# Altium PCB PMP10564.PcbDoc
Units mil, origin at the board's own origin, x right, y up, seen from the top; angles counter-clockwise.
Board outline 4200 x 3100 mil, 2 copper layers (Top Layer, Bottom Layer), stack 62 mil thick; 67 components, 34 nets, 153 pads, 5 vias.
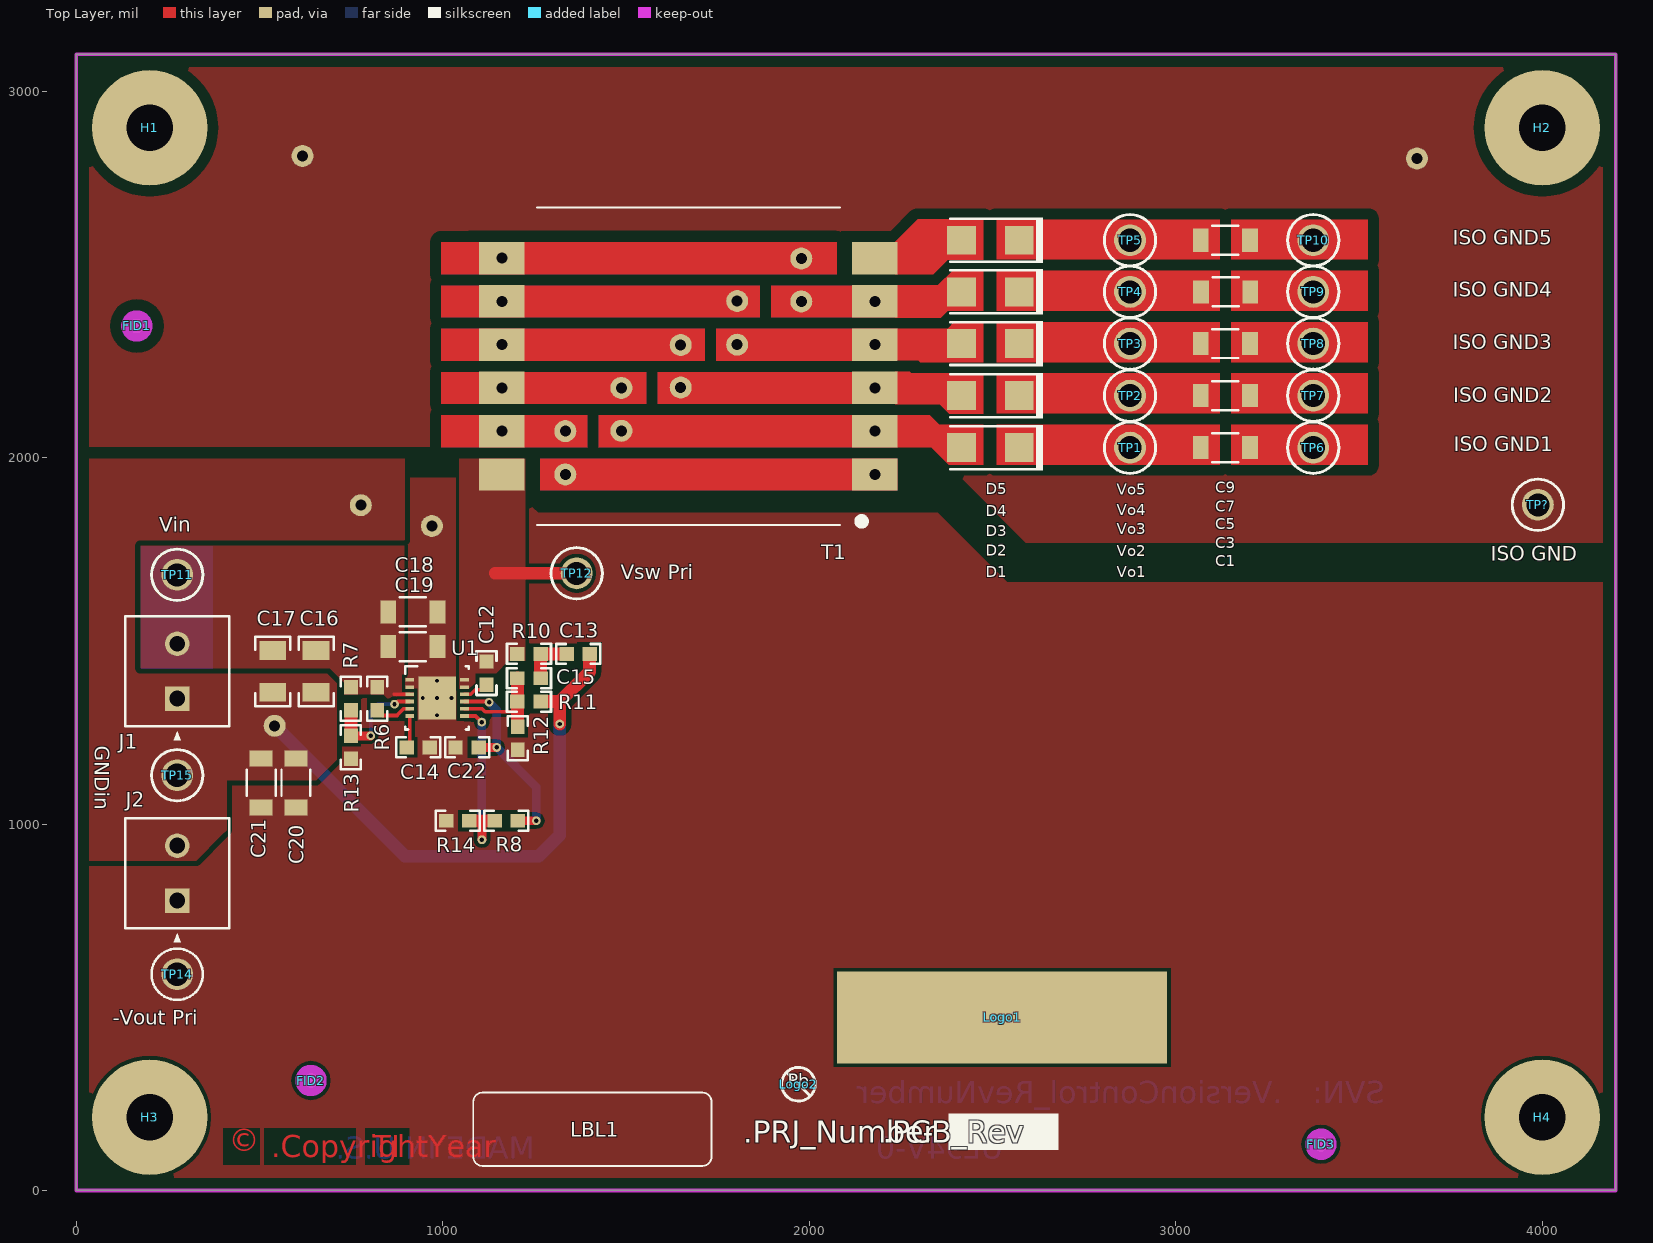
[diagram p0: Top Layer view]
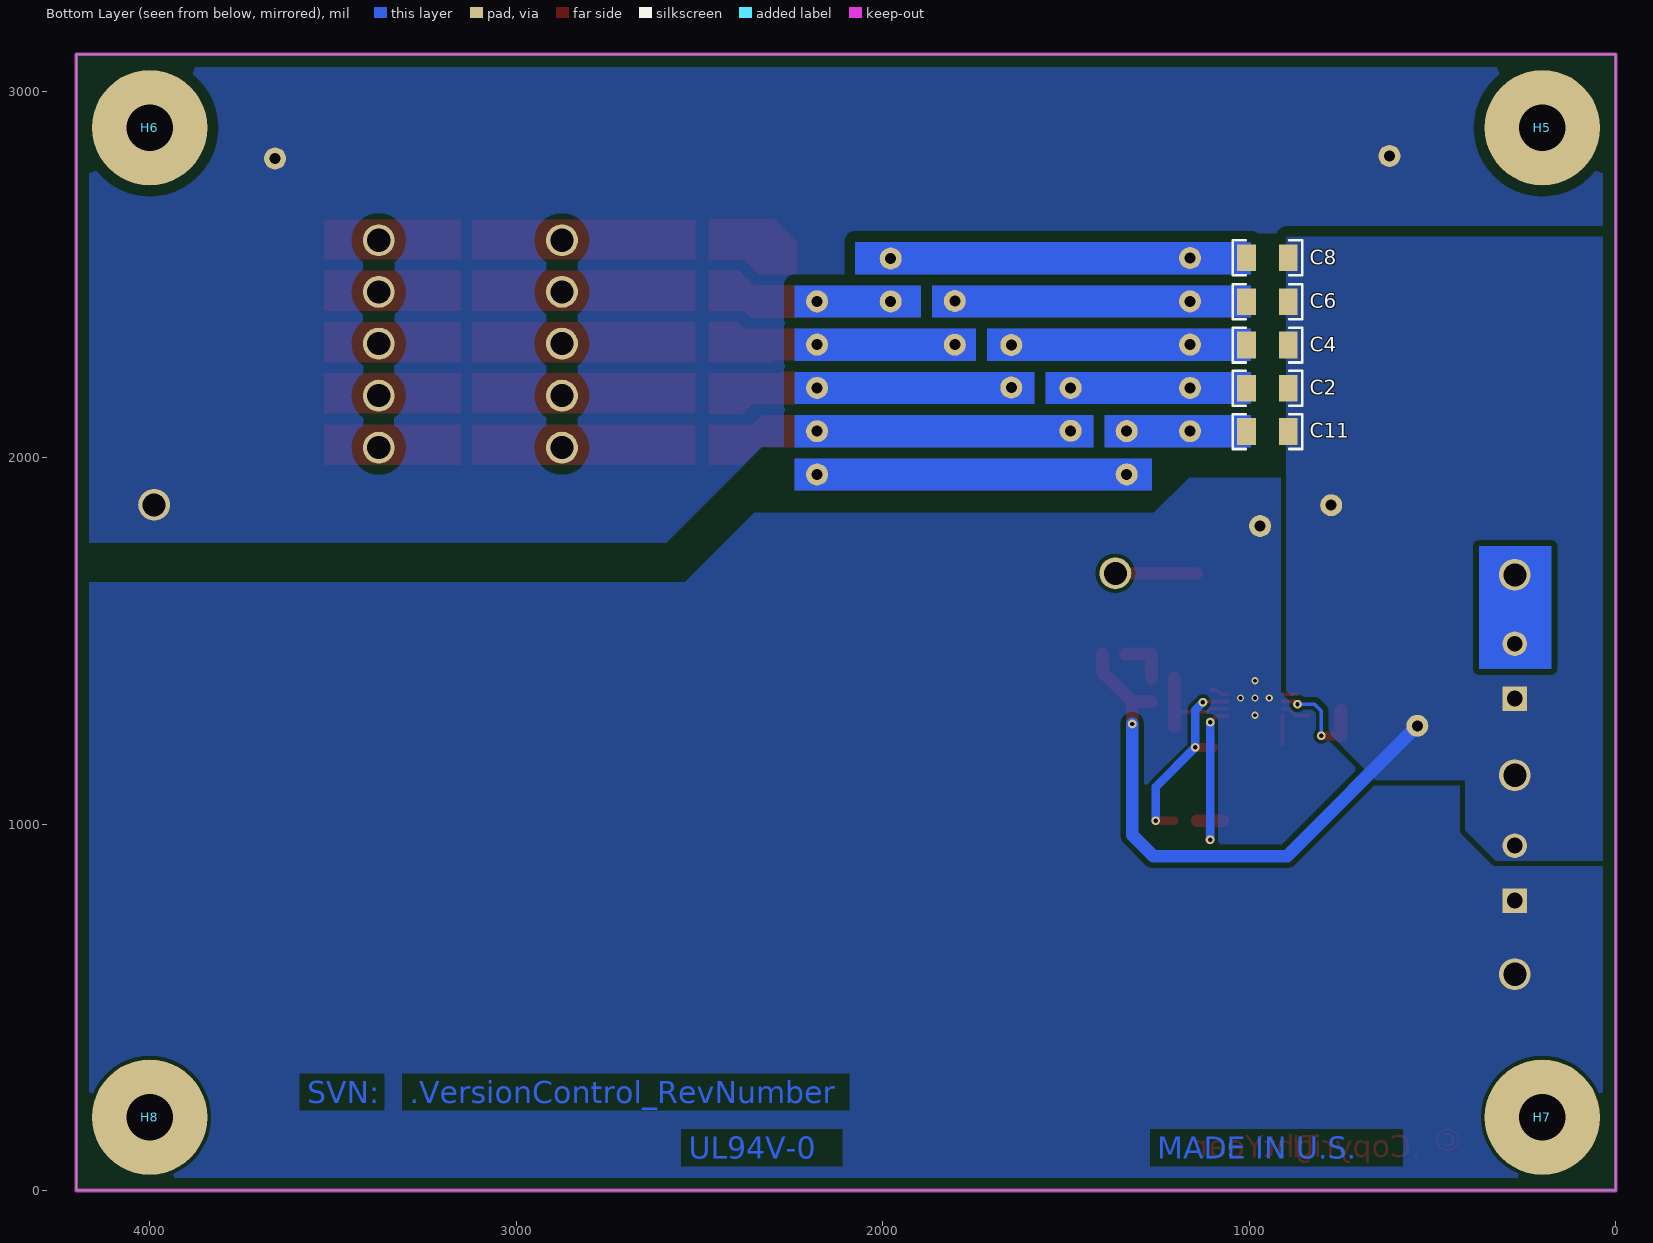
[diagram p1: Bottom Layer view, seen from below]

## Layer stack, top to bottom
Top Layer: signal copper 1.4
Dielectric: core 59.2, FR-4, Dk 4.8
Bottom Layer: signal copper 1.4

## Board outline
0,0 4200,0 4200,3100 0,3100

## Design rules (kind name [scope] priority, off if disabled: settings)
AcuteAngle [All] p1: minimum=4.50000000000000E+0001 checktracksonly=FALSE
AssemblyTestPointUsage [All] p1: valid=2
Clearance "Clearance_ISO GND Bottom" [InNet('ISO GND') vs InNet('GND')] p1: gap=30
Clearance Clearance_KeepOut [OnLayer('Keep-Out Layer')] p2: gap=30
Clearance Clearance_GND [InNet('GND')] p3: gap=15
Clearance Clearance_-Vout [InNet('-VOUT')] p4: gap=10
Clearance "Clearance_ISO GND" [InNet('ISO GND')] p5: gap=30
Clearance Clearance_BoardEdge_MountingHoles [OnCopper and InComponentClass('Mounting Holes') vs IsKeepOut] p6: gap=35
Clearance Clearance_BoardEdge_Poly [OnCopper and InPoly vs IsKeepOut] p7: gap=25
Clearance Clearance_BoardEdge [OnCopper and Not InComponentClass('Logo') and not InComponentClass('FiducialMark') and not InRegion(1000,500,4000,800) and Not IsKeepout vs IsKeepOut] p8: gap=25
Clearance Clearance_Poly [InPolygon] p9: gap=9
Clearance [All] p10: gap=9
ComponentClearance ComponentClearance_Shunt [InComponentClass('Header') vs InComponentClass('Shunt')] p1: gap=0 collisioncheckmode=3 verticalgap=0 showdistances=FALSE
ComponentClearance ComponentClearance_MountingHoles_FiducialMarks [InComponentClass('Mounting Holes') vs InComponentClass('FiducialMark')] p2: gap=30 collisioncheckmode=3 verticalgap=10 showdistances=FALSE
ComponentClearance ComponentClearance_Logo [InComponentClass('Logo')] p3: gap=30 collisioncheckmode=3 verticalgap=10 showdistances=FALSE
ComponentClearance ComponentClearance_ScrewToNut [(HasFootprint('NY PMS 440 0025 PH')) vs (HasFootprint('Keystone_1902C'))] p4: gap=5 collisioncheckmode=3 verticalgap=10 showdistances=FALSE
ComponentClearance ComponentClearance_MountingHoles [InComponentClass('Mounting Holes')] p5: gap=200 collisioncheckmode=3 verticalgap=100000 showdistances=FALSE
ComponentClearance ComponentClearance_SmallPassives [HasFootprint('0201*') or HasFootprint('0402*') or HasFootprint('0508') or HasFootprint('0603*') or HasFootprint('0612') or HasFootprint('0805*') or HasFootprint('0815*') or HasFootprint('0830*') or HasFootprint('1206*') or HasFootprint('1210*') or HasFootprint('1808*') or HasFootprint('1812*') or HasFootprint('1825*') or HasFootprint('2010*') or HasFootprint('2220*') or HasFootprint('2225*') or HasFootprint('2512*') or HasFootprint('2728*') or HasFootprint('3518*') vs HasFootprint('0201*') or HasFootprint('0402*') or HasFootprint('0508') or HasFootprint('0603*') or HasFootprint('0612') or HasFootprint('0805*') or HasFootprint('0815*') or HasFootprint('0830*') or HasFootprint('1206*') or HasFootprint('1210*') or HasFootprint('1808*') or HasFootprint('1812*') or HasFootprint('1825*') or HasFootprint('2010*') or HasFootprint('2220*') or HasFootprint('2225*') or HasFootprint('2512*') or HasFootprint('2728*') or HasFootprint('3518*')] p6: gap=20 collisioncheckmode=3 verticalgap=10 showdistances=FALSE
ComponentClearance ComponentClearance_THtoSMT [IsThruComponent vs IsSMTComponent] p7: gap=30 collisioncheckmode=3 verticalgap=30 showdistances=FALSE
ComponentClearance ComponentClearance_THtoTH [IsThruComponent vs IsThruComponent] p8: gap=15 collisioncheckmode=3 verticalgap=30 showdistances=FALSE
ComponentClearance [All] p9: gap=20 collisioncheckmode=3 verticalgap=10 showdistances=FALSE
DiffPairsRouting [All] p1: maxlimit=100 minlimit=10 mostfreqgap=10 maxuncoupledlength=1000
FabricationTestPointUsage TestPointUsage [All] p1: valid=2 allowmultiple=FALSE
FabricationTestpoint Testpoint [All] p1: side=3 testpointundercomponent=TRUE minsize=40 maxsize=100 preferedsize=60 minholesize=0 maxholesize=40 preferedholesize=32 testpointgrid=1 allowsidetop=TRUE allowsidebottom=TRUE usegrid=TRUE gridtolerance=0.01
FanoutControl Fanout_LCC [IsLCC] p1: bgadir=Out bgaviamode=Centered fanoutstyle=Auto fanoutdirection=Alternating viagrid=1 // Fanout_LCC (Default Rule)
FanoutControl Fanout_BGA [IsBGA] p2: bgadir=Out bgaviamode=Centered fanoutstyle=Auto fanoutdirection=Alternating viagrid=1 // Fanout_BGA (Default Rule)
FanoutControl Fanout_Default [All] p4: bgadir=Out bgaviamode=Centered fanoutstyle=Auto fanoutdirection=Alternating viagrid=1 // Fanout_Default (Default Rule)
FanoutControl Fanout_Small [(CompPinCount < 5)] p5: bgadir=Out bgaviamode=Centered fanoutstyle=Auto fanoutdirection=OutThenIn viagrid=1 // Fanout_Small (Default Rule)
HoleSize [All] p1: absolutevalues=TRUE maxlimit=251 minlimit=8 maxpercent=80.000 minpercent=20.000
MinimumAnnularRing MinimumAnnularRing_ThermalPadVias [IsVia and InAnyComponent] p1: minimumring=5
MinimumAnnularRing [All] p2: minimumring=5
MinimumSolderMaskSliver MinimumSolderMaskSliver_Logo [InComponentClass('Logo') vs InComponentClass('Logo')] p1: minsoldermaskwidth=0.7
MinimumSolderMaskSliver [All] p2: minsoldermaskwidth=3.94
PlaneClearance [All] p1: clearance=15
PlaneConnect [All] p1: planeconnectstyle=Direct reliefexpansion=10 reliefentries=4 reliefconductorwidth=10 reliefairgap=10
PolygonConnect [All] p1: connectstyle=Direct reliefconductorwidth=10 reliefentries=4 polygonreliefangle="90 Angle" airgapwidth=10
RoutingVias ThermalPadVias [IsVia and InAnyComponent] p1: holewidth=7.87 width=19.68 viastyle="Through Hole" minholewidth=7.87 minwidth=19.68 maxholewidth=12.99 maxwidth=23.62
RoutingVias [All] p2: holewidth=16 width=34 viastyle="Through Hole" minholewidth=7.87 minwidth=26 maxholewidth=40 maxwidth=65
SMDToCorner [All] p1: distance=30000
SilkToSilkClearance SilkToSilkClearance_Pb-FreeLogo [(HasFootprint('Pb-Free_Overlay_Medium') OR HasFootprint('Pb-Free_Overlay_Small')) vs (HasFootprint('Pb-Free_Overlay_Medium') OR HasFootprint('Pb-Free_Overlay_Small'))] p1: silktosilkclearance=0
SilkToSilkClearance [All] p2: silktosilkclearance=5
SilkscreenOverComponentPads [All] p1: minsilkscreentomaskgap=5
SolderMaskExpansion [All] p1: expansion=1.97
Width [All] p1: maxlimit=100 minlimit=6 preferedwidth=10 checkconnectedcopper=TRUE
13 further rules are at their usual default settings.

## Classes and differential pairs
component class "PMP10564 Schematics": C1 C2 C3 C4 C5 C6 C7 C8 C9 C11 C12 C13 C14 C15 C16 C17 C18 C19 C20 C21 C22 D1 D2 D3 D4 D5 J1 J2 R6 R7 R8 R10 R11 R12 R13 R14 T1 TP1 TP2 TP3 TP4 TP5 TP6 TP7 TP8 TP9 TP10 TP11 TP12 TP14 TP15 TP? U1
component class "Mounting Holes": H1 H2 H3 H4
component class Logo: Logo1
component class PMP10564_Hardware_ANSI-B: FID1 FID2 FID3 H1 H2 H3 H4 H5 H6 H7 H8 LBL1 Logo1 Logo2
component class FiducialMark: FID1 FID2 FID3
component class Label: LBL1

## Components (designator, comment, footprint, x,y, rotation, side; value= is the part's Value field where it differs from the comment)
C1 "C3216X7R1V106M160AC" 1206_190 3135,2027 r0 top
C2 "VJ1206A102JXGAT5Z" 1206 950,2189 r180 bottom
C3 "C3216X7R1V106M160AC" 1206_190 3135,2169 r0 top
C4 "VJ1206A102JXGAT5Z" 1206 950,2307 r180 bottom
C5 "C3216X7R1V106M160AC" 1206_190 3135,2311 r0 top
C6 "VJ1206A102JXGAT5Z" 1206 950,2425 r180 bottom
C7 "C3216X7R1V106M160AC" 1206_190 3136,2452 r0 top
C8 "VJ1206A102JXGAT5Z" 1206 950,2545 r180 bottom
C9 "C3216X7R1V106M160AC" 1206_190 3135,2593 r0 top
C11 "VJ1206A102JXGAT5Z" 1206 950,2071 r180 bottom
C12 "C0603C104J3RAC" 0603 1119,1412 r270 top
C13 "GRM188R72A104KA35D" 0603 1369,1464 r180 top
C14 "GRM188R71C223KA01D" 0603 933,1209 r0 top
C15 "GRM188R71E102KA01D" 0603 1235,1398 r180 top
C16 "GRM31CR61H225KA88L" 1206 654,1416.32 r270 top
C17 "GRM31CR61H225KA88L" 1206 536,1416.32 r270 top
C18 "GRM31CR72A225KA73L" 1206_190 918,1579 r0 top
C19 "GRM31CR72A225KA73L" 1206_190 918,1484 r0 top
C20 "CL31A106KBHNNNE" 1206_190 599,1112 r270 top
C21 "CL31A106KBHNNNE" 1206_190 504,1112 r270 top
C22 "GRM188R71E105KA12D" 0603 1066,1209 r180 top
D1 "ES1D-13-F" SMA 2494,2027 r180 top
D2 "ES1D-13-F" SMA 2494,2169 r180 top
D3 "ES1D-13-F" SMA 2494,2311 r180 top
D4 "ES1D-13-F" SMA 2494,2452 r180 top
D5 "ES1D-13-F" SMA 2494,2593 r180 top
FID1 "Fiducial" Fiducial10-20 165,2359 r0 top
FID2 "Fiducial" Fiducial10-20 640,300 r0 top
FID3 "Fiducial" Fiducial10-20 3396,126 r0 top
H1 "NY PMS 440 0025 PH" "NY PMS 440 0025 PH" 200,2900 r0 top locked
H2 "NY PMS 440 0025 PH" "NY PMS 440 0025 PH" 4000,2900 r0 top locked
H3 "NY PMS 440 0025 PH" "NY PMS 440 0025 PH" 200,200 r0 top locked
H4 "NY PMS 440 0025 PH" "NY PMS 440 0025 PH" 4000,200 r0 top locked
H5 "1902C" Keystone_1902C 200,2900 r180 bottom locked
H6 "1902C" Keystone_1902C 4000,2900 r180 bottom locked
H7 "1902C" Keystone_1902C 200,200 r180 bottom locked
H8 "1902C" Keystone_1902C 4000,200 r180 bottom locked
J1 "1727010" PhoenixConact_1727010 275,1417 r90 top
J2 "1727010" PhoenixConact_1727010 275,866 r90 top
LBL1 "Size: 0.65\" x 0.20 \"" Label_650x200 1408,167 r0 top
Logo1 "Texas Instruments" TI_Stacked_SolderMask_Small 2526,472 r0 top
Logo2 "Pb-Free Symbol" Pb-Free_Overlay_Small 1970,290 r0 top
R6 "CRCW06031M50FKEA" 0603 821,1342 r270 top
R7 "CRCW0603205KFKEA" 0603 749,1342 r90 top
R8 "CRCW06030000Z0EA" 0603 1172.55,1009 r180 top
R10 "RT0603DRE0710KL" 0603 1235,1464 r0 top
R11 "CRCW0603280KFKEA" 0603 1235,1334 r0 top
R12 "CRCW060320K0FKEA" 0603 1204,1234 r90 top
R13 "CRCW060318K2FKEA" 0603 749,1209 r90 top
R14 "DNP" 0603 1040.55,1009 r0 top
T1 "" PCBComponent_1 1670,2249 r180 top
TP1 "Vo1" Keystone5014 2875,2027 r270 top
TP2 "Vo2" Keystone5014 2875,2169 r0 top
TP3 "Vo3" Keystone5014 2875,2311 r90 top
TP4 "Vo4" Keystone5014 2875,2452 r0 top
TP5 "Vo5" Keystone5014 2875,2593 r90 top
TP6 "ISO GND1" Keystone5011 3375,2027 r270 top
TP7 "ISO GND2" Keystone5011 3375,2169 r0 top
TP8 "ISO GND3" Keystone5011 3375,2311 r90 top
TP9 "ISO GND4" Keystone5011 3375,2452 r0 top
TP10 "ISO GND5" Keystone5011 3375,2593 r90 top
TP11 "Vin" Keystone5010 275,1680 r0 top
TP12 "Vsw Pri" Keystone5014 1365,1684 r0 top
TP14 "-Vout Pri" Keystone5126 275,590 r0 top
TP15 "GNDin" Keystone5011 275,1133 r0 top
TP? "ISO GND" Keystone5011 3988,1871 r0 top
U1 "LM5160DNT" DNT0012B 984,1344 r0 top

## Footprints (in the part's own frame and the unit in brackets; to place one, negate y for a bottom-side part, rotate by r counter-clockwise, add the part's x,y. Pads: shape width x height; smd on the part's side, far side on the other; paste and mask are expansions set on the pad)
0603 [mm] "0603 from SM-752 data"
  rect 1x0.95 smd: 1(-0.8,0) 2(0.8,0)
  silkscreen extent -1.52,-0.69 1.52,0.69, body extent -0.87,-0.47 0.87,0.47, height 0.85
1206 [mm] "1206 from SM-752 data"
  rect 1.3x1.85 smd: 1(-1.45,0) 2(1.45,0)
  silkscreen extent -2.4,-1.21 2.4,1.21, body extent -1.7,-0.9 1.7,0.9, height 1.35
1206_190 [mm] "1206_190"
  rect 1.1x1.6 smd: 1(-1.7,0) 2(1.7,0)
  silkscreen extent -0.9,-1 0.9,1, body extent -1.75,-0.95 1.75,0.95, height 1.9
DNT0012B [mm] "SON, 12-Leads, Body 4x4mm, Pitch 0.5mm"
  rect 0.6x0.25 smd: 1(-1.9,1.25) 2(-1.9,0.75) 3(-1.9,0.25) 4(-1.9,-0.25) 5(-1.9,-0.75) 6(-1.9,-1.25) 7(1.9,-1.25) 8(1.9,-0.75) 9(1.9,-0.25) 10(1.9,0.25) 11(1.9,0.75) 12(1.9,1.25)
  rect 2.6x3 smd paste-1.3: 13(0,0)
  silkscreen extent -2.2,-2.2 2.2,2.2, body extent -2.05,-2.05 2.05,2.05, height 0.81
Fiducial10-20 [mm]
  round 1 smd mask+0.5: 1(0,0)
  Top Layer keep-out circle w1.178: c0,0 r0.5
Keystone5010 [mil] "Keystone Multipurpose loops"
  round 87 hole 63: 1(0,0)
  silkscreen extent -70,-70 70,70, body extent -63,-63 63,62, height 319
Keystone5011 [mil] "Keystone Multipurpose loops"
  round 87 hole 63: 1(0,0)
  silkscreen extent -70,-70 70,70, body extent -63,-63 63,62, height 319
Keystone5014 [mil] "Keystone Multipurpose loops"
  round 87 hole 63: 1(0,0)
  silkscreen extent -70,-70 70,70, body extent -63,-63 63,62, height 319
Keystone5126 [mil] "Keystone Multipurpose loops"
  round 87 hole 63: 1(0,0)
  silkscreen extent -70,-70 70,70, body extent -63,-63 63,62, height 319
Keystone_1902C [mil] "Hex Standoff, 4-40 threaded, nylon"
  body extent -145,-126 146,126, height 501
Label_650x200 [mil] "Thermal Transfer Label"
  silkscreen extent -325,-100 325,100, body extent -326,-101 326,101, height 1
"NY PMS 440 0025 PH" [mm] "4-40 nylon screw and mounting hole"
  round 8 hole 3.2: 1(0,0)
  body extent -3.3,-3.3 3.3,3.3, height 2.69
Pb-Free_Overlay_Small [mil]
  silkscreen extent -46,-46 46,46
PCBComponent_1 [mm]
  rect 3.15x2.25 smd: 1(-12.925,7.5) 2(-12.925,4.5) 3(-12.925,1.5) 4(-12.925,-1.5) 5(-12.925,-4.5) 6(-12.925,-7.5) 7(12.925,-7.5) 8(12.925,-4.5) 9(12.925,-1.5) 10(12.925,1.5) 11(12.925,4.5) 12(12.925,7.5)
  silkscreen extent -12.26,-11 10.5,11
PhoenixConact_1727010 [mm]
  rect 1.7x1.7 hole 1.1: 1(-1.905,0)
  round 1.7 hole 1.1: 2(1.905,0)
  silkscreen extent -4.8,-3.6 3.81,3.6, body extent -3.81,-3.6 3.81,3.7, height 8.52
SMA [mm] "Molded Diode, 2-Leads, Body 4.3x2.6mm, IPC Medium Density, based on OnSemi component dimensions and land pattern"
  rect 2x2 smd: 1(-2,0) 2(2,0)
  silkscreen extent -3.66,-1.57 2.79,1.57, body extent -2.6,-1.3 2.6,1.3, height 2.42
TI_Stacked_SolderMask_Small [mil]
  rect 900x250 smd paste-125 mask-125: 0(0,0)

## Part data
C1 C3 C5 C7 C9: "CAP, CERM, 10 µF, 35 V, +/- 20%, X7R, 1206_190"
C2 C4 C6 C8 C11: "CAP, CERM, 1000pF, 1000V, +/-5%, C0G/NP0, 1206"
C12: "CAP, CERM, 0.1uF, 25V, +/-5%, X7R, 0603"
C13: "CAP, CERM, 0.1 µF, 100 V, +/- 10%, X7R, 0603"
C14: "CAP, CERM, 0.022uF, 16V, +/-10%, X7R, 0603"
C15: "CAP, CERM, 1000 pF, 25 V, +/- 10%, X7R, 0603"
C16 C17: "CAP, CERM, 2.2uF, 50V, +/-10%, X5R, 1206"
C18 C19: "CAP, CERM, 2.2uF, 100V, +/-10%, X7R, 1206_190"
C20 C21: "CAP, CERM, 10 µF, 50 V, +/- 10%, X5R, 1206_190"
C22: "CAP, CERM, 1uF, 25V, +/-10%, X7R, 0603"
D1 D2 D3 D4 D5: "Diode, Ultrafast, 200V, 1A, SMA"
FID1 FID2 FID3: "Fiducial mark.  There is nothing to buy or mount."
H1 H2 H3 H4: "Machine Screw, Round, #4-40 x 1/4, Nylon, Philips panhead"
H5 H6 H7 H8: "Standoff, Hex, 0.5\"L #4-40 Nylon"
J1 J2: "Conn Term Block, 2POS, 3.81mm, TH"
LBL1: library part THT-14-423-10, "Thermal Transfer Printable Labels, 0.650\" W x 0.200\" H - 10,000 per roll"
Logo1: library part TI_Logo, "Texas Instrument Corporate Signature"
Logo2: library part Pb-Free
R6: "RES, 1.50 M, 1%, 0.1 W, 0603"
R7: "RES, 205 k, 1%, 0.1 W, 0603"
R8: "RES, 0, 5%, 0.1 W, 0603"
R10: "RES, 10.0 k, 0.5%, 0.1 W, 0603"
R11: "RES, 280 k, 1%, 0.1 W, 0603"
R12: "RES, 20.0 k, 1%, 0.1 W, 0603"
R13: "RES, 18.2k ohm, 1%, 0.1W, 0603"
R14: library part CRCW06030000Z0EA, "RES, 0, 5%, 0.1 W, 0603"
T1: library part "VP5 Versapac TXMR", "Six-Winding Versatile Transformer"
TP1 TP2 TP3 TP4 TP5 TP12: library part 5014, "Test Point, Multipurpose, Yellow, TH"
TP6 TP7 TP8 TP9 TP10 TP15 TP?: library part 5011, "Test Point, Multipurpose, Black, TH"
TP11: library part 5010, "Test Point, Multipurpose, Red, TH"
TP14: library part 5126, "Test Point, Multipurpose, Green, TH"
U1: "Wide Input 65V, 1.5A Synchronous Step-Down DC-DC Converter, DNT0012B"

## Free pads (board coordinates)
  round 60 hole 30: 0(541,1268) 0(617,2823) 0(776,1870) 0(970,1813) 0(1978,2543) 0(2178.86,2426.17) 0(3658,2816) 1(1978,2426) 1(2178.86,2308.06) 2(1803,2427) 2(2178.86,2189.94) 3(1803,2308) 3(2178.86,2071.83) 4(1649,2307) 4(2178.86,1953.72) 5(1161.14,2071.83) 5(1649,2191) 6(1161.14,2189.94) 6(1487,2190) 7(1161.14,2308.06) 7(1487,2073) 8(1161.14,2426.17) 8(1334,2072) 9(1161.14,2544.28) 9(1334,1954)
  round 24 hole 12: 0(803,1241) 0(868,1327) 0(1106,1278) 0(1106.55,957) 0(1126,1332) 0(1147,1209) 0(1255,1009) 0(1319,1273)

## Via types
v1: diameter 20, hole 10, Top Layer to Bottom Layer, 5 vias

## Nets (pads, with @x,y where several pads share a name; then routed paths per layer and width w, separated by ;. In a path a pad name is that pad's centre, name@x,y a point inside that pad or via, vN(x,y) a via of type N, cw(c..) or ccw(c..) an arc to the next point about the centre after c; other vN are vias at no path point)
1: pad.4@2178.86,1953.72 pad.9@1334,1954 T1.1
2: D1.2 pad.3@2178.86,2071.83 pad.7@1487,2073 T1.2
3: D2.2 pad.2@2178.86,2189.94 pad.5@1649,2191 T1.3
4: D3.2 pad.1@2178.86,2308.06 pad.3@1803,2308 T1.4
5: D4.2 pad.0@2178.86,2426.17 pad.1@1978,2426 T1.5
6: D5.2 T1.6
7: C8.1 pad.0@1978,2543 pad.9@1161.14,2544.28 T1.7
8: C6.1 pad.2@1803,2427 pad.8@1161.14,2426.17 T1.8
9: C4.1 pad.4@1649,2307 pad.7@1161.14,2308.06 T1.9
10: C2.1 pad.6 T1.10
11: C11.1 pad.5@1161.14,2071.83 pad.8@1334,2072 T1.11
-VOUT: C14.2 C18.2 C19.2 C20.2 C21.2 C22.2 J2.1 pad.0@970,1813 R12.1 R13.1 R14.1 TP14.1 U1.1 U1.2 U1.13
  other v1: 984,1296.76 944.63,1344 984,1344 1023.37,1344 984,1391.24
BST: C12.2 U1.10 | length 50.7
  Top Layer w10: U1.10 1075.84,1353.84 1088,1366 C12.2@1104.5,1366
EN: pad.0@803,1241 pad.0@868,1327 R7.1 R13.2 U1.4 | length 295.6
  Top Layer w10: pad.0@877.16,1334.16 U1.4
  Top Layer w24: R13.2 pad.0@802.5,1240.5
  Top Layer w35: R13.2 R7.1
  Bottom Layer w10: pad.0@803,1241 803,1308.25 821.75,1327 pad.0@868,1327
FB: C15.2 R11.1 R12.2 U1.8 | length 279.9
  Top Layer w10: U1.8 1106.76,1314.47 1115.23,1306 1203.2,1306
  Top Layer w35: R11.1 C15.2 ; R12.2 R11.1@1204,1333.5
FPWM: pad.0@1106,1278 pad.0@1106.55,957 R8.2 R14.2 U1.7 | length 496.4
  Top Layer w10: U1.7 1089.21,1294.79 pad.0@1106,1278
  Top Layer w24: pad.0@1106.55,957 1106.55,1009
  Top Layer w35: R14.2 1106.55,1009 R8.2
  Bottom Layer w24: pad.0@1106,1278 1106,957.55 pad.0@1106.55,957
GND: C2.2 C4.2 C6.2 C8.2 C11.2 C13.1 C16.2 C17.2 C20.1 C21.1 J1.1 J2.2 pad.0@541,1268 pad.0@776,1870 pad.0@1319,1273 R11.2 TP15.1 | length 1529.7
  Top Layer w35: R11.2 1319,1334 ; pad.0@1319,1273 1319,1334 ; C13.1 1400.5,1415.5 1319,1334
  Bottom Layer w35: pad.0@541,1268 897,912 1261,912 1319,970 pad.0@1319,1273
"ISO GND": pad.0@617,2823 pad.0@3658,2816 TP?.1
"ISO GND1": C1.2 TP6.1
"ISO GND2": C3.2 TP7.1
"ISO GND3": C5.2 TP8.1
"ISO GND4": C7.2 TP9.1
"ISO GND5": C9.2 TP10.1
RON: R6.2 U1.5 | length 82.5
  Top Layer w10: R6.2@835.5,1296 873.88,1296 ; 875,1296 873.88,1296 ; U1.5 892.35,1314.47 873.88,1296
SS: C14.1 U1.6 | length 78.1
  Top Layer w10: C14.1@909.2,1216.69 U1.6
"SW PRI": C12.1 R10.1 T1.12 TP12.1 U1.11 U1.12 | length 221
  Top Layer w35: 1144,1684 TP12.1
VCC: C22.1 pad.0@1126,1332 pad.0@1147,1209 pad.0@1255,1009 R8.1 U1.9 | length 545
  Top Layer w10: U1.9 1123.84,1334.16 pad.0@1126,1332
  Top Layer w24: C22.1 pad.0@1147,1209 ; R8.1 pad.0@1255,1009
  Bottom Layer w24: pad.0@1126,1332 1147,1311 1147,1209 1255,1101 pad.0@1255,1009
VIN: C16.1 C17.1 C18.1 C19.1 J1.2 R6.1 R7.2 TP11.1 U1.3 | length 42
  Top Layer w10: 867.16,1353.84 U1.3
VO1: C1.1 D1.1 TP1.1
VO2: C3.1 D2.1 TP2.1
VO3: C5.1 D3.1 TP3.1
VO4: C7.1 D4.1 TP4.1
VO5: C9.1 D5.1 TP5.1
VRIPL: C13.2 C15.1 R10.2 | length 137
  Top Layer w35: C15.1 R10.2 C13.2
pads on no net: FID1.1 FID2.1 FID3.1 H1.1 H2.1 H3.1 H4.1 Logo1.0

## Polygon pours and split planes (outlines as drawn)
-VOUT on Bottom Layer "Bottom Layer- -Vout" (solid, remove dead copper, pour order 16): 0,1918 0,1945 11,1945 1164,1945 1260,1849 1265,1849 2350,1849 2540,1659 4200,1659 4200,1649 4200,0 0,0 0,1918
"ISO GND" on Bottom Layer "Bottom Layer-ISO GND" (solid, remove dead copper, pour order 14): 0,2030 4,2030 2329,2030 2591,1768 2610,1768 4200,1768 4200,1780 4200,3100 0,3100 0,3073 0,2030
GND on Bottom Layer "Bottom Layer-GND" (solid, remove dead copper, pour order 12): 327,900 410,983 410,1120 654,1120 710,1176 898,1364 898,1841 898,2600 900,2602 846,2602 0,2602 0,900 1,900
-VOUT on Top Layer "Top Layer- -Vout" (solid, remove dead copper, pour order 15): 0,1945 24,1945 1045,1945 1164,1945 1260,1849 1283,1849 2350,1849 2540,1659 2560,1659 4200,1659 4200,1644 4200,0 4196,0 0,0 0,1945
"ISO GND" on Top Layer "Top Layer-ISO GND" (solid, remove dead copper, pour order 13): 0,2030 4,2030 2329,2030 2591,1768 2610,1768 4200,1768 4200,1780 4200,3100 0,3100 0,3073 0,2030
GND on Top Layer "Top Layer-GND" (solid, remove dead copper, pour order 11): 896,1997 885,1997 0,1997 0,1982 0,900 13,900 327,900 397,970 410,983 410,1120 654,1120 710,1176 710,1188 710,1424 896,1610 896,1723 896,1732
VIN on Top Layer "Top Layer-Vin" (solid, remove dead copper, pour order 9): 175,1759 895,1759 895,1364 920,1364 920,1343 848,1343 837,1354 731,1354 731,1385 691,1425 175,1425
"SW PRI" on Top Layer "Top Layer-SW PRI" (solid, remove dead copper, pour order 10): 1045,1997 1225,1997 1225,1445 1178,1445 1145,1412 1088,1412 1088,1386 1071,1369 1045,1369

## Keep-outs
Keep-Out Layer:
  the board outline again, w10
  text ".Layer_Name" at 577,-858.49 h60

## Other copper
Top Layer:
  rectangle net "ISO GND1": 3150,1980 3525,2090
  rectangle net "ISO GND2": 3150,2120 3525,2230
  rectangle net "ISO GND3": 3150,2260 3525,2370
  rectangle net "ISO GND4": 3150,2400 3525,2510
  rectangle net "ISO GND5": 3150,2540 3525,2650
  rectangle net VO1: 2510,1980 3120,2090
  rectangle net VO2: 2510,2120 3120,2230
  rectangle net VO3: 2510,2260 3120,2370
  rectangle net VO4: 2510,2400 3120,2510
  rectangle net VO5: 2510,2540 3120,2650
  rectangle net 1: 1265,1910 2240,1998
  rectangle net 2: 1425,2028 2240,2116
  rectangle net 3: 1585,2146 2240,2234
  rectangle net 4: 1745,2264 2240,2352
  rectangle net 5: 1895,2382 2240,2470
  rectangle net 11: 995,2028 1395,2116
  rectangle net 10: 995,2146 1555,2234
  rectangle net 9: 995,2264 1715,2352
  rectangle net 8: 995,2382 1865,2470
  rectangle net 7: 995,2500 2075,2588
  region net 2: 2235,2116 2329,2116 2355,2090 2475,2090 2475,1980 2381,1980 2333,2028 2235,2028
  region net 3: 2235,2234 2274,2234 2278,2230 2475,2230 2475,2120 2382,2120 2356,2146 2235,2146
  region net 4: 2235,2352 2377,2352 2395,2370 2475,2370 2475,2260 2302,2260 2297,2265 2235,2265
  region net 5: 2351,2470 2391,2510 2475,2510 2475,2400 2377,2400 2359,2382 2235,2382 2235,2470
  region net 6: 2235,2500 2338,2500 2378,2540 2475,2540 2475,2650 2296,2650 2235,2589
  text ".CopyrightYear" at 532,90 h60
  text "TI" at 808,90 h60
  text "©" at 415,86.48 h105
  text ".Layer_Name" at 577,-858.49 h60
Bottom Layer:
  rectangle net VIN: 175,1423 373,1759
  rectangle net 5: 1895,2382 2240,2470
  rectangle net 4: 1745,2264 2240,2352
  rectangle net 3: 1585,2146 2240,2234
  rectangle net 2: 1425,2028 2240,2116
  rectangle net 1: 1265,1910 2240,1998
  rectangle net 11: 995,2028 1395,2116
  rectangle net 10: 995,2146 1555,2234
  rectangle net 9: 995,2264 1715,2352
  rectangle net 8: 995,2382 1865,2470
  rectangle net 7: 995,2500 2075,2588
  text ".VersionControl_RevNumber" at 3291,238.5 h60
  text "SVN:" at 3570,238.5 h60
  text "MADE IN U.S." at 1250,86.5 h60
  text "UL94V-0" at 2529.5,86.5 h60
  text ".Layer_Name" at 577,-858.49 h60

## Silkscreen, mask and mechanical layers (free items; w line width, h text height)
Top Overlay:
  region: 2680,210 2380,210 2380,110 2680,110
  text ".PRJ_Number" at 1820,130.01 h60
  text ".PCB_Rev" at 2200,130.01 h60
  text "-" at 2310,130.01 h60
  text ".Layer_Name" at 577,-858.49 h60
Bottom Overlay:
  text ".Layer_Name" at 577,-858.49 h60
Top Paste:
  text ".Layer_Name" at 577,-858.49 h60
Bottom Paste:
  text ".Layer_Name" at 577,-858.49 h60
Top Solder:
  rectangle: 793.26,2030 965,2116
  rectangle: 793.26,2146 965,2234
  rectangle: 793.26,2264 965,2352
  rectangle: 793.26,2382 965,2470
  rectangle: 793.26,2500 965,2588
  rectangle: 3555.26,1980 3727,2090
  rectangle: 3555.26,2120 3727,2230
  rectangle: 3555.26,2260 3727,2370
  rectangle: 3555.26,2400 3727,2510
  rectangle: 3555.26,2541 3727,2650
  rectangle: 3150,2540 3525,2650
  rectangle: 3150,2400 3525,2510
  rectangle: 3150,2260 3525,2370
  rectangle: 3150,2120 3525,2230
  rectangle: 3150,1980 3525,2090
  rectangle: 2510,1980 3120,2090
  rectangle: 2510,2120 3120,2230
  rectangle: 2510,2260 3120,2370
  rectangle: 2510,2400 3120,2510
  rectangle: 2510,2540 3120,2650
  rectangle: 1895,2382 2240,2470
  rectangle: 1745,2264 2242,2352
  rectangle: 1585,2146 2242,2234
  rectangle: 1425,2028 2241,2116
  rectangle: 1265,1910 2242,1998
  rectangle: 995,2028 1395,2116
  rectangle: 995,2146 1555,2234
  rectangle: 995,2264 1715,2352
  rectangle: 995,2382 1865,2470
  rectangle: 995,2500 2075,2588
  region: 2235,2116 2329,2116 2355,2090 2475,2090 2475,1980 2381,1980 2333,2028 2235,2028
  region: 2235,2234 2274,2234 2278,2230 2475,2230 2475,2120 2382,2120 2356,2146 2235,2146
  region: 2235,2352 2377,2352 2395,2370 2475,2370 2475,2260 2302,2260 2297,2265 2235,2265
  region: 2235,2470 2351,2470 2391,2510 2475,2510 2475,2400 2377,2400 2359,2382 2235,2382
  region: 2296,2650 2475,2650 2475,2540 2378,2540 2338,2500 2235,2500 2235,2589
  text ".Layer_Name" at 577,-858.49 h60
  text ".Layer_Name" at 577,-858.49 h60
Bottom Solder:
  rectangle: 1895,2382 2240,2470
  rectangle: 1745,2264 2240,2352
  rectangle: 1585,2146 2240,2234
  rectangle: 1425,2028 2240,2116
  rectangle: 1265,1910 2240,1998
  rectangle: 995,2028 1395,2116
  rectangle: 995,2146 1555,2234
  rectangle: 995,2264 1715,2352
  rectangle: 995,2382 1865,2470
  rectangle: 995,2500 2075,2588
  text ".Layer_Name" at 577,-858.49 h60
Drill Guide:
  text ".Layer_Name" at 577,-858.49 h60
M1 Board Outline:
  the board outline again, w10
  text ".Layer_Name" at 577,-858.49 h60
M2 Board Dimensions:
  rectangle: 0,-285.5 125,-160.5
  rectangle: 125,-410.5 500,-285.5
  lines w7: 0,-285.5 1000,-285.5 ; 125,-410.5 125,-160.5 ; 250,-410.5 250,-160.5 ; 500,-410.5 500,-160.5 ; 750,-410.5 750,-160.5 ; 0,-410.5 1000,-410.5 1000,-160.5 0,-160.5 0,-410.5
  text ".Layer_Name" at 577,-858.49 h60
M3 3D STEP Top:
  text ".Layer_Name" at 577,-858.49 h60
M4 3D STEP Bottom:
  text ".Layer_Name" at 577,-858.49 h60
M5 Assembly Top:
  lines w10: -292,-930.17 6308,-930.17 ; -292,-726.83 6310,-726.83 ; -292,-523.5 -292,-1133.5 3713,-1133.5 6310,-1133.5 6310,-523.5 -291.5,-523.5 -291.5,-1133.5 1284,-1133.5 ; 2173,-1133.5 2173,-523.5 ; 3440,-726.83 3440,-523.5 ; 4280,-726.83 4280,-523.5 ; 4902,-1140 4902,-937.17
  text "COMPONENTS MARKED 'DNP' SHOULD NOT BE POPULATED." at 1153.5,-318.5 h60
  text "ASSEMBLY VARIANT:" at 1153,-434 h60
  text ".VariantName" at 2189,-434 h60
  text "PCB VIEWED FROM TOP SIDE" at -228.5,-655.67 h60
  text "BOARD #:" at 2248,-655.67 h60
  text ".PRJ_Number" at 2793.5,-655.67 h60
  text "REV:" at 3638,-655.67 h60
  text ".PCB_Rev" at 3929.5,-655.67 h60
  text "SVN REV:" at 4476,-655.67 h60
  text ".VersionControl_RevNumber" at 4982,-655.67 h60
  text "IGNORE ->" at -228.5,-858.49 h60
  text "PLOT NAME =" at -228.5,-1064.34 h60
  text ".plot_File_Name" at 577,-1064.34 h60
  text "GENERATED    :" at 2250,-1064.34 h60
  text ".Print_Date" at 3119.5,-1064.34 h60
  text ".Print_Time" at 3848.5,-1064.34 h60
  text "TEXAS INSTRUMENTS" at 5113,-1064.34 h60
M6 Assembly Bottom:
  lines w10: -292.5,-727.33 6309.5,-727.33 ; -290.5,-930.67 6309.5,-930.67 ; 1115.5,-1140.5 1115.5,-937.67 ; 1737.5,-727.33 1737.5,-524 ; 2577.5,-727.33 2577.5,-524 ; 3844.5,-1134 3844.5,-524 ; 4733.5,-1134 6309,-1134 6309,-524 -292.5,-524 -292.5,-1134 2304.5,-1134 6309.5,-1134 6309.5,-524
  text "COMPONENTS MARKED 'DNP' SHOULD NOT BE POPULATED." at 6102,-318 h60
  text ".VariantName" at 5058,-434 h60
  text "ASSEMBLY VARIANT:" at 6097,-434 h60
  text ".VersionControl_RevNumber" at 1035.5,-656.17 h60
  text "SVN REV:" at 1541.5,-656.17 h60
  text ".PCB_Rev" at 2088,-656.17 h60
  text "REV:" at 2379.5,-656.17 h60
  text ".PRJ_Number" at 3224,-656.17 h60
  text "BOARD #:" at 3769.5,-656.17 h60
  text "PCB VIEWED FROM BOTTOM SIDE" at 6246,-656.17 h60
  text "IGNORE ->" at 2547.85,-858.49 h60
  text "TEXAS INSTRUMENTS" at 904.5,-1064.84 h60
  text ".Print_Time" at 2169,-1064.84 h60
  text ".Print_Date" at 2898,-1064.84 h60
  text "GENERATED    :" at 3767.5,-1064.84 h60
  text ".plot_File_Name" at 5440.5,-1064.84 h60
  text "PLOT NAME =" at 6246,-1064.84 h60
M9 Title Sheet:
  drawing of 57 lines, arcs and shapes, not listed
  text "1" at 739.84,8036.5 h70
  text "2" at 3235.5,8036.5 h70
  text "3" at 5724.84,8036.5 h70
  text "4" at 8231.51,8036.5 h70
  text "5" at 10730.5,8036.5 h70
  text "6" at 13235.5,8036.5 h70
  text "A" at -416.5,6893.5 h70
  text "A" at 14383.5,6893.5 h70
  text "B" at -416.5,4513.5 h70
  text "B" at 14383.5,4513.5 h70
  text "C" at -416.5,2138.5 h70
  text "C" at 14383.5,2138.5 h70
  text "PROJECT TITLE:" at 11343.5,277.5 h45
  text ".PRJ_Title" at 11393.5,144.17 h70
  text "DESIGNED FOR:" at 11343.5,-23.5 h45
  text ".PRJ_Customer" at 11393.5,-163.5 h70
  text "D" at -416.5,-231.5 h70
  text "D" at 14383.5,-231.5 h70
  text "FILE NAME:" at 11343.5,-323.5 h45
  text ".PCB_File_Name_No_Path" at 11393.5,-443.5 h70
  text "Texas Instruments (TI) and/or its licensors do not warrant the accuracy or completeness of this specification" at 6374,-605.34 h45
  text "ENGINEER:" at 11343.5,-613.5 h45
  text "LAYOUT BY:" at 12848.5,-613.5 h45
  text "or any information contained therein. TI and/or its licensors do not warrant that this design will meet" at 6329.01,-718 h45
  text ".PRJ_Engineer" at 11393.5,-768.49 h70
  text ".PCB_Layout" at 12899,-768.49 h70
  text "the specifications, will be suitable for your application or fit for any particular purpose, or will operate in" at 6329.01,-830.67 h45
  text ".Layer_Name" at 577,-858.49 h60
  text "ALTIUM DESIGNER VERSION:" at 12848.5,-923.5 h45
  text "an implementation. TI and/or its licensors do not warrant that the design is production worthy. You should" at 6329.01,-943.33 h45
  text "completely validate and test your design implementation to confirm the system functionality for your application." at 6374,-1056 h45
  text ".print_Scale" at 11393.5,-1056.83 h70
  text ".Application_BuildNumber" at 12899,-1056.83 h70
  text "1" at 739.84,-1263.5 h70
  text "2" at 3235.5,-1263.5 h70
  text "3" at 5724.84,-1263.5 h70
  text "4" at 8231.51,-1263.5 h70
  text "5" at 10730.5,-1263.5 h70
  text "6" at 13235.5,-1263.5 h70
M10 Fab Notes:
  drawing of 185 lines, arcs and shapes, not listed
  text "DESIGN INFORMATION" at 12381.02,5910 h60
  text "MIN. TRACK WIDTH:" at 11736.46,5730 h60
  text "8" at 12832.7,5730 h60
  text "MIL" at 12987.46,5730 h60
  text "MIN. CLEARANCE:" at 11736.46,5598 h60
  text "0.2" at 12772.7,5598 h60
  text "mm" at 12987.46,5598 h60
  text "MIN. VIA PAD SIZE:" at 11736.46,5466 h60
  text "24" at 12802.71,5466 h60
  text "MIL" at 12987.46,5466 h60
  text "0.05mm (2MIL)" at 12431.46,5324.29 h60
  text "MINIMUM ANNULAR RING" at 11407.23,5320 h60
  text "EXTERNAL" at 13139.46,5320 h60
  text "PER" at 11607.23,5202 h60
  text "IPC-D-275 CLASS 2 LEVEL C" at 11827.23,5202 h60
  text "MIL, HOLES" at 13315.46,5089.71 h60
  text "+/-" at 12923,5089 h60
  text "+/-" at 13777,5089 h60
  text "REGISTRATION TOLERANCES:" at 11407.23,5084 h60
  text "METAL" at 12607,5084 h60
  text "5" at 13183.2,5084 h60
  text "3" at 14016.2,5084 h60
  text "MIL" at 14132.46,5084 h60
  text "MATERIAL:" at 11332.46,4874.54 h60
  text "FR-4 High Tg" at 12318.9,4734.21 h60
  text "FR-408" at 11753.46,4725.64 h60
  text "X" at 12165.46,4725.64 h60
  text "OTHER" at 13241.46,4725.64 h60
  text "62 MIL (1.6mm) +/-10%" at 12073.56,4562.92 h60
  text "THICKNESS:" at 11407.23,4558.64 h60
  text "X" at 11945.4,4558.64 h60
  text "OTHER" at 13358.46,4558.64 h60
  text "TOLERANCE:" at 11407.23,4400.64 h60
  text "X" at 12246.53,4400.64 h60
  text "ANSI IPC-6012 TYPE 3 CLASS 2" at 12433.48,4400.64 h60
  text "OTHER +/-" at 12433.46,4244.64 h60
  text "BOW & TWIST:" at 11407.23,4087.64 h60
  text "X" at 12246.53,4087.64 h60
  text "ANSI IPC-6012 TYPE 3 CLASS 2" at 12433.48,4087.64 h60
  text "OTHER +/-" at 12433.46,3929.13 h60
  text "DRILLING:" at 11332.46,3790.64 h60
  text "REFERENCE:" at 11407.23,3673.64 h60
  text "X" at 12055.46,3673.64 h60
  text "AS SHOWN" at 12242.46,3673.64 h60
  text "X" at 12956.46,3673.64 h60
  text "NC_DRILL FILES" at 13093.46,3673.64 h60
  text "PTH MIN COPPER THICKNESS:" at 11407.23,3515.64 h60
  text "X" at 12757.46,3515.64 h60
  text "1MIL" at 12894.46,3515.64 h60
  text "OTHER" at 13391.46,3515.64 h60
  text "BOARD FINISH:" at 11332.46,3356.64 h60
  text "SILKSCREEN:" at 11487.68,3238.64 h60
  text "X" at 12436.46,3238.64 h60
  text "TOP" at 12562.46,3238.64 h60
  text "X" at 12946.46,3238.64 h60
  text "BOTTOM" at 13073.46,3238.64 h60
  text "SILKSCREEN COLOR:" at 11487.68,3071.64 h60
  text "X" at 12435.42,3071.64 h60
  text "WHITE" at 12562.46,3071.64 h60
  text "OTHER" at 13073.46,3071.64 h60
  text "SOLDER RESIST COLOR:" at 11487.68,2901.64 h60
  text "X" at 12055.42,2742.44 h60
  text "GREEN" at 12182.46,2742.44 h60
  text "BLUE" at 12773.46,2742.44 h60
  text "OTHER" at 13311.46,2742.44 h60
  text "IMMERSION GOLD (ENIG)" at 12393.46,2553.92 h60
  text "ENEPIG" at 13731,2550.64 h60
  text "SURFACE FINISH:" at 11332.46,2549.64 h60
  text "X" at 12206.51,2549.64 h60
  text "IMM. TIN/SILVER OR EQUIV" at 11662,2392.64 h60
  text "OTHER" at 13093.46,2392.64 h60
  text "ARRAY/PANEL:" at 11332.46,2213.64 h60
  text "CUT AND TRIM PER MECH LAYER 1" at 12393.46,2209.35 h60
  text "N.C. ROUTE" at 12393.46,2057.64 h60
  text "X" at 13072.46,2057.64 h60
  text "V. SCORE" at 13259.46,2057.64 h60
  text "CERTIFICATION:" at 11332.46,1920.64 h60
  text "MATERIALS AND WORKMANSHIP FOR ALL PCBS" at 12057.46,1920.64 h60
  text "TO MEET OR EXCEED THE REQUIREMENTS OF:" at 12057.46,1822.64 h60
  text "X" at 11683.96,1686.13 h60
  text "ANSI IPC-A-600F CLASS ->" at 11822.96,1686.13 h60
  text "X" at 13462.02,1686.13 h60
  text "2" at 13580.96,1686.14 h60
  text "1" at 13265.96,1684.64 h60
  text "3" at 13934.96,1684.64 h60
  text "X" at 11686.02,1526.64 h60
  text "UL 94V-0" at 11822.96,1526.64 h60
  text "X" at 12498.02,1526.64 h60
  text "RoHS" at 12634.96,1526.64 h60
  text "OTHER" at 13279.36,1526.64 h60
  text "PER ORDER" at 13676.42,1526.64 h60
  text "ADDITIONAL REQUIREMENTS:" at 11332.46,1385.64 h60
  text "MICROSECTION:" at 11407.23,1270.64 h60
  text "YES" at 12312.96,1270.64 h60
  text "REQUIRED" at 13174.46,1114.49 h60
  text "BARE BOARD ELEC. TEST:" at 11407.23,1111.64 h60
  text "NONE" at 12712.96,1111.64 h60
  text "X" at 13047.46,1111.64 h60
  text "PER ORDER" at 13766.46,1111.64 h60
  text "MANUFACTURER'S UL:" at 11407.23,954.64 h60
  text "RAIL" at 12572.96,950.35 h60
  text "METAL" at 13064.77,950.35 h60
  text "X" at 13440,950 h60
  text "SILK" at 13576.46,950.35 h60
  text ".Layer_Name" at 577,-858.49 h60
M11 Gerber Information:
  lines w10: -292,-930.17 6308,-930.17 ; -292,-726.83 6310,-726.83 ; -292,-523.5 -292,-1133.5 3713,-1133.5 6310,-1133.5 6310,-523.5 -291.5,-523.5 -291.5,-1133.5 1284,-1133.5 ; 2173,-1133.5 2173,-523.5 ; 3440,-726.83 3440,-523.5 ; 4280,-726.83 4280,-523.5 ; 4902,-1140 4902,-937.17
  text "ALL ARTWORK VIEWED FROM TOP SIDE" at -228.5,-655.67 h60
  text "BOARD #:" at 2248,-655.67 h60
  text ".PRJ_Number" at 2793.5,-655.67 h60
  text "REV:" at 3638,-655.67 h60
  text ".PCB_Rev" at 3929.5,-655.67 h60
  text "SVN REV:" at 4476,-655.67 h60
  text ".VersionControl_RevNumber" at 4982,-655.67 h60
  text "LAYER NAME =" at -228.5,-858.49 h60
  text "PLOT NAME =" at -228.5,-1064.34 h60
  text ".plot_File_Name" at 577,-1064.34 h60
  text "GENERATED    :" at 2250,-1064.34 h60
  text ".Print_Date" at 3119.5,-1064.34 h60
  text ".Print_Time" at 3848.5,-1064.34 h60
  text "TEXAS INSTRUMENTS" at 5113,-1064.34 h60
M12 Stackup:
  lines w6: 11360,7460 13910,7460 ; 11360,7564.4 13910,7564.4 ; 11300,6975 ccw(c11334,6975) 11334,6941 13936,6941 ccw(c13936,6975) 13970,6975 13970,7681 ccw(c13936,7681) 13936,7715 11334,7715 ccw(c11334,7681) 11300,7681 11300,6975
  text "The Stackup Legend below this is static." at 11605.5,7874.5 h60
  text "If you change the stackup, update the Legend." at 11615.5,7784.5 h60
  text "Layer Stack Up Detail for: Ref_Design.PcbDoc" at 11360,7597.1 h57
  text "Layer" at 11360,7525.4 h24
  text "Gerber" at 12255.81,7525.4 h24
  text "Copper" at 12819.33,7525.4 h24
  text "Dielectric" at 13422.04,7525.4 h24
  text "Name" at 11360,7477.4 h24
  text "Document" at 12255.81,7477.4 h24
  text "Thickness" at 12819.33,7477.4 h24
  text "Material" at 13422.04,7477.4 h24
  text "Top Solder Mask" at 11360,7384.44 h34
  text "(.GTS)" at 12255.81,7384.44 h34
  text "Solder Resist" at 13422.04,7384.44 h34
  text "Top Layer" at 11360,7287.69 h34
  text "(.GTL)" at 12255.81,7287.69 h34
  text "1.4mil" at 12819.33,7287.69 h34
  text "FR-4" at 13422.04,7239.31 h34
  text "Bottom Layer" at 11360,7190.94 h34
  text "(.GBL)" at 12255.81,7190.94 h34
  text "1.4mil" at 12819.33,7190.94 h34
  text "Bottom Solder Mask" at 11360,7094.19 h34
  text "(.GBS)" at 12255.81,7094.19 h34
  text "Solder Resist" at 13422.04,7094.19 h34
  text ".Layer_Name" at 577,-858.49 h60
M13 Component Bodies Top:
  text ".Layer_Name" at 577,-858.49 h60
M14 Component Bodies Bottom:
  text ".Layer_Name" at 577,-858.49 h60
M15 Courtyards Top:
  text ".Layer_Name" at 577,-858.49 h60
M16 Courtyards Bottom:
  text ".Layer_Name" at 577,-858.49 h60
Drill Drawing:
  text ".legend" at 5122.5,725.5 h60
  text "Drill Table" at 5147.5,540.5 h60
  text ".Layer_Name" at 577,-858.49 h60

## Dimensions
0,0 to 0,3100 on M2 Board Dimensions
0,0 to 4200,0 on M2 Board Dimensions
0,-410.5 to 1000,-410.5 on M2 Board Dimensions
